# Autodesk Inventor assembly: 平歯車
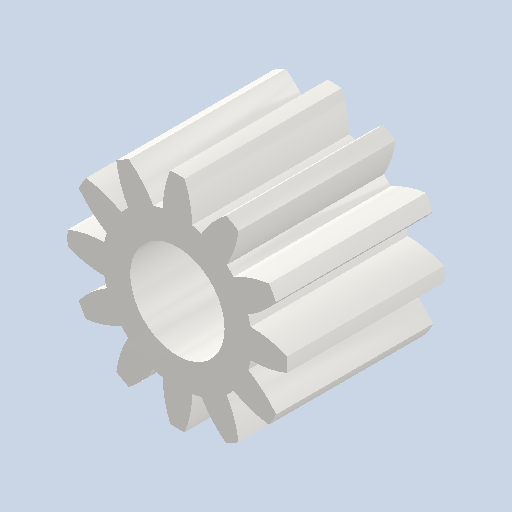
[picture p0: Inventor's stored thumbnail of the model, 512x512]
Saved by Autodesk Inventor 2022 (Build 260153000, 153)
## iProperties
ClientObjectVersion: 1
Created: 2024-12
Part Number: 平歯車
Document SubType Name: Assembly
Designer: jsat7
Categories: <?xml version="1.0" encoding="UTF-16"?> <MemberInstance><Categories><FamilyTemplate/><ParamToTemplateMap><ParamToTemplate><ParamToTemplate CategoryParameter="//
Author: jsat7
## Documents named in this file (2)
- C:\Users\jsat7\OneDrive\デスクトップ\CAD 長田\Assembly5\デザイン アクセラレータ\平歯車1.iam
- C:\Users\jsat7\OneDrive\デスクトップ\CAD 長田\Assembly5\デザイン アクセラレータ\平歯車11.ipt
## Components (1 placed, 1 different names)
1. 平歯車1:1
